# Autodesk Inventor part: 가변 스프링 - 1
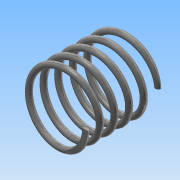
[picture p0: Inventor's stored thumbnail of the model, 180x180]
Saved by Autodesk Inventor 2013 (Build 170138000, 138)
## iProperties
Created: 2016-01
Part Number: 가변 스프링 - 1
Material: 스테인리스강
Document SubType Name: Modeling
Designer: Administrator
Mass: 8.61881 g
Surface Area: 21.6344 cm^2
Volume: 1.06668 cm^3
Density: 8.08 g/cm^3
Author: Administrator
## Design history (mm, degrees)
sketch "스케치1"
  geometry: L1 (0, 0)-(11, 0); L2 (11, 0)-(11, 25.358); L3 (11, 25.358)-(0, 25.358); L4 (0, 25.358)-(0, 0); C1 r 1 at (11, 0)
  constraints: 8 end point, 2 parallel, 1 centre point, 1 coincident, 1 horizontal, 1 perpendicular
  dimensions: "d0" = 2 diameter of C1; "d2" = 22 diameter of L2 L4; "d3" = 25.35829 distance between parallel lines of L1 L3 (derived)
feature "코일1" sketch "스케치1" pitch "d4" = 10; turns "d6" = 5; dims "d5" = 25.35829 (= d3), "d7" = 0, angle "d8" = 90 deg, angle "d9" = 90 deg, "d10" = 0, "d11" = 0
feature "분할1"
node "작업 평면1"
feature "분할2"
node "솔리드1"
other parameters: "d12" = 90 deg
